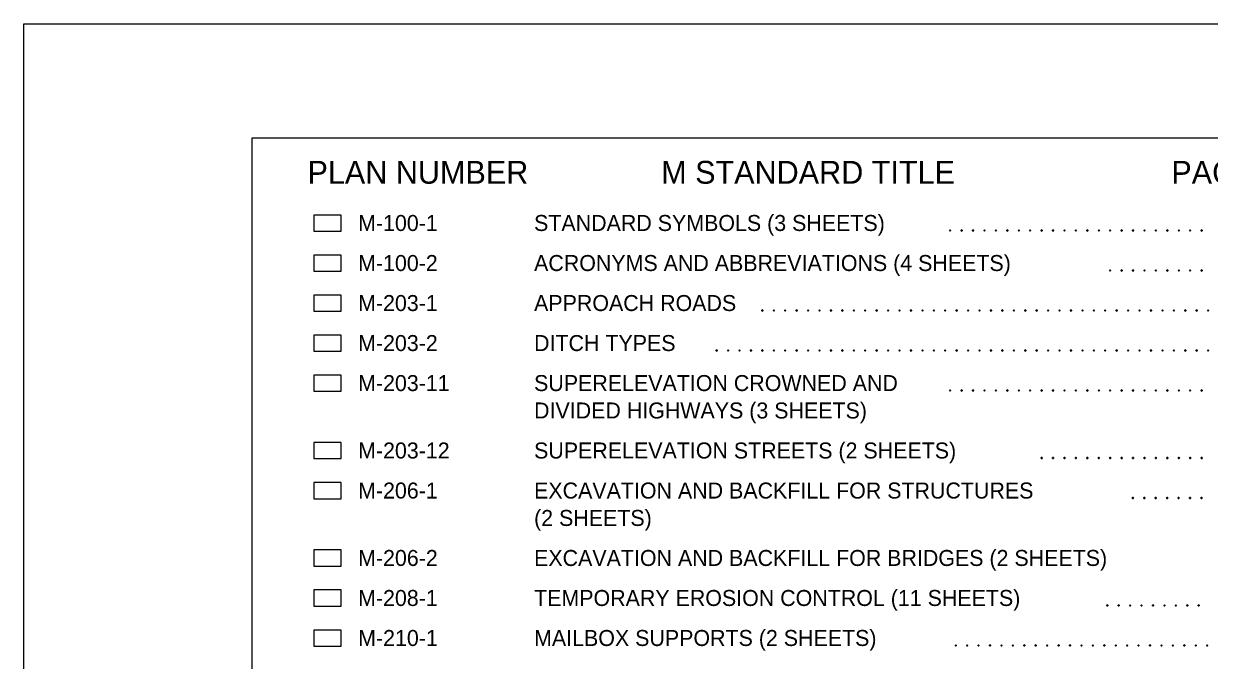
# Model space of a CAD drawing. Extents: x 0 to 1.42, y 0 to 0.92.
# Drawn here: x 0 to 0.4322, y 0.6845 to 0.9167 of the extents above; entities that cross this region are included whole.
import ezdxf

# ---------------------------------------------------------------- set-up
doc = ezdxf.new("R2010")
doc.units = 0
for name, color, linetype in [('DRAFT_Text-Notes', 7, 'Continuous'), ('DRAFT_Text-Titles', 7, 'Continuous'), ('SHEET_Lines', 7, 'Continuous'), ('SHEET_Plot Boundary', 7, 'Continuous')]:
    doc.layers.add(name, color=color, linetype=linetype)

msp = doc.modelspace()

# ---------------------------------------------------------------- linework, layer by layer
at = {"layer": 'DRAFT_Text-Notes'}
for centre in [(0.33776, 0.84128), (0.34192, 0.84128), (0.34609, 0.84128), (0.35026, 0.84128), (0.35442, 0.84128), (0.35859, 0.84128), (0.36276, 0.84128), (0.36692, 0.84128), (0.37109, 0.84128), (0.37526, 0.84128), (0.37942, 0.84128), (0.38359, 0.84128), (0.38776, 0.84128), (0.39192, 0.84128), (0.39609, 0.84128), (0.40026, 0.84128), (0.40442, 0.84128), (0.40859, 0.84128), (0.41276, 0.84128), (0.41276, 0.84128), (0.41692, 0.84128), (0.42109, 0.84128), (0.42526, 0.84128), (0.42942, 0.84128), (0.39609, 0.82669), (0.40026, 0.82669), (0.40442, 0.82669), (0.40859, 0.82669), (0.41276, 0.82669), (0.41276, 0.82669), (0.41692, 0.82669), (0.42109, 0.82669), (0.42526, 0.82669), (0.42942, 0.82669), (0.26929, 0.8121), (0.27346, 0.8121), (0.27763, 0.8121), (0.28179, 0.8121), (0.28596, 0.8121), (0.29013, 0.8121), (0.29429, 0.8121), (0.29846, 0.8121), (0.30263, 0.8121), (0.30679, 0.8121), (0.31096, 0.8121), (0.31513, 0.8121), (0.31929, 0.8121), (0.32346, 0.8121), (0.32346, 0.8121), (0.32763, 0.8121), (0.33179, 0.8121), (0.33596, 0.8121), (0.34013, 0.8121), (0.34429, 0.8121), (0.34846, 0.8121), (0.35263, 0.8121), (0.35679, 0.8121), (0.36096, 0.8121), (0.36513, 0.8121), (0.36929, 0.8121), (0.37346, 0.8121), (0.37763, 0.8121), (0.38179, 0.8121), (0.38596, 0.8121), (0.39013, 0.8121), (0.39429, 0.8121), (0.39846, 0.8121), (0.40263, 0.8121), (0.40679, 0.8121), (0.41096, 0.8121), (0.41096, 0.8121), (0.41513, 0.8121), (0.41929, 0.8121), (0.42346, 0.8121), (0.42763, 0.8121), (0.43179, 0.8121), (0.25263, 0.79751), (0.25679, 0.79751), (0.26096, 0.79751), (0.26513, 0.79751), (0.26929, 0.79751), (0.27346, 0.79751), (0.27763, 0.79751), (0.28179, 0.79751), (0.28596, 0.79751), (0.29013, 0.79751), (0.29429, 0.79751), (0.29846, 0.79751), (0.29846, 0.79751), (0.30263, 0.79751), (0.30679, 0.79751), (0.31096, 0.79751), (0.31513, 0.79751), (0.31929, 0.79751), (0.32346, 0.79751), (0.32763, 0.79751), (0.33179, 0.79751), (0.33596, 0.79751), (0.34013, 0.79751), (0.34429, 0.79751), (0.34846, 0.79751), (0.35263, 0.79751), (0.35679, 0.79751), (0.36096, 0.79751), (0.36513, 0.79751), (0.36929, 0.79751), (0.37346, 0.79751), (0.37763, 0.79751), (0.38179, 0.79751), (0.38596, 0.79751), (0.38596, 0.79751), (0.39013, 0.79751), (0.39429, 0.79751), (0.39846, 0.79751), (0.40263, 0.79751), (0.40679, 0.79751), (0.41096, 0.79751), (0.41513, 0.79751), (0.41929, 0.79751), (0.42346, 0.79751), (0.42763, 0.79751), (0.43179, 0.79751), (0.33776, 0.78292), (0.34192, 0.78292), (0.34609, 0.78292), (0.35026, 0.78292), (0.35442, 0.78292), (0.35859, 0.78292), (0.36276, 0.78292), (0.36692, 0.78292), (0.37109, 0.78292), (0.37526, 0.78292), (0.37942, 0.78292), (0.38359, 0.78292), (0.38776, 0.78292), (0.38776, 0.78292), (0.39192, 0.78292), (0.39609, 0.78292), (0.40026, 0.78292), (0.40442, 0.78292), (0.40859, 0.78292), (0.41276, 0.78292), (0.41692, 0.78292), (0.42109, 0.78292), (0.42526, 0.78292), (0.42942, 0.78292), (0.37109, 0.75832), (0.37526, 0.75832), (0.37942, 0.75832), (0.38359, 0.75832), (0.38776, 0.75832), (0.38776, 0.75832), (0.39192, 0.75832), (0.39609, 0.75832), (0.40026, 0.75832), (0.40442, 0.75832), (0.40859, 0.75832), (0.41276, 0.75832), (0.41692, 0.75832), (0.42109, 0.75832), (0.42526, 0.75832), (0.42942, 0.75832), (0.40435, 0.74373), (0.40852, 0.74373), (0.41269, 0.74373), (0.41269, 0.74373), (0.41685, 0.74373), (0.42102, 0.74373), (0.42519, 0.74373), (0.42935, 0.74373), (0.39503, 0.70455), (0.3992, 0.70455), (0.40336, 0.70455), (0.40753, 0.70455), (0.4117, 0.70455), (0.41586, 0.70455), (0.42003, 0.70455), (0.4242, 0.70455), (0.42836, 0.70455), (0.33978, 0.68996), (0.34394, 0.68996), (0.34811, 0.68996), (0.35228, 0.68996), (0.35644, 0.68996), (0.36061, 0.68996), (0.36478, 0.68996), (0.36894, 0.68996), (0.37311, 0.68996), (0.37728, 0.68996), (0.38144, 0.68996), (0.38561, 0.68996), (0.38978, 0.68996), (0.39394, 0.68996), (0.39811, 0.68996), (0.40228, 0.68996), (0.40644, 0.68996), (0.41061, 0.68996), (0.41478, 0.68996), (0.41894, 0.68996), (0.42311, 0.68996), (0.42728, 0.68996), (0.43144, 0.68996)]:
    msp.add_circle(centre, 0.000208, dxfattribs=at)
for centre, start, end in [((0.33776, 0.84128), 0, 180), ((0.33776, 0.84128), 180, 0), ((0.34192, 0.84128), 0, 180), ((0.34192, 0.84128), 180, 0), ((0.34609, 0.84128), 0, 180), ((0.34609, 0.84128), 180, 0), ((0.35026, 0.84128), 0, 180), ((0.35026, 0.84128), 180, 0), ((0.35442, 0.84128), 0, 180), ((0.35442, 0.84128), 180, 0), ((0.35859, 0.84128), 0, 180), ((0.35859, 0.84128), 180, 0), ((0.36276, 0.84128), 0, 180), ((0.36276, 0.84128), 180, 0), ((0.36692, 0.84128), 0, 180), ((0.36692, 0.84128), 180, 0), ((0.37109, 0.84128), 0, 180), ((0.37109, 0.84128), 180, 0), ((0.37526, 0.84128), 0, 180), ((0.37526, 0.84128), 180, 0), ((0.37942, 0.84128), 0, 180), ((0.37942, 0.84128), 180, 0), ((0.38359, 0.84128), 0, 180), ((0.38359, 0.84128), 180, 0), ((0.38776, 0.84128), 0, 180), ((0.38776, 0.84128), 180, 0), ((0.39192, 0.84128), 0, 180), ((0.39192, 0.84128), 180, 0), ((0.39609, 0.84128), 0, 180), ((0.39609, 0.84128), 180, 0), ((0.40026, 0.84128), 0, 180), ((0.40026, 0.84128), 180, 0), ((0.40442, 0.84128), 0, 180), ((0.40442, 0.84128), 180, 0), ((0.40859, 0.84128), 0, 180), ((0.40859, 0.84128), 180, 0), ((0.41276, 0.84128), 0, 180), ((0.41276, 0.84128), 0, 180), ((0.41276, 0.84128), 180, 0), ((0.41276, 0.84128), 180, 0), ((0.41692, 0.84128), 0, 180), ((0.41692, 0.84128), 180, 0), ((0.42109, 0.84128), 0, 180), ((0.42109, 0.84128), 180, 0), ((0.42526, 0.84128), 0, 180), ((0.42526, 0.84128), 180, 0), ((0.42942, 0.84128), 0, 180), ((0.42942, 0.84128), 180, 0), ((0.39609, 0.82669), 0, 180), ((0.39609, 0.82669), 180, 0), ((0.40026, 0.82669), 0, 180), ((0.40026, 0.82669), 180, 0), ((0.40442, 0.82669), 0, 180), ((0.40442, 0.82669), 180, 0), ((0.40859, 0.82669), 0, 180), ((0.40859, 0.82669), 180, 0), ((0.41276, 0.82669), 0, 180), ((0.41276, 0.82669), 0, 180), ((0.41276, 0.82669), 180, 0), ((0.41276, 0.82669), 180, 0), ((0.41692, 0.82669), 0, 180), ((0.41692, 0.82669), 180, 0), ((0.42109, 0.82669), 0, 180), ((0.42109, 0.82669), 180, 0), ((0.42526, 0.82669), 0, 180), ((0.42526, 0.82669), 180, 0), ((0.42942, 0.82669), 0, 180), ((0.42942, 0.82669), 180, 0), ((0.26929, 0.8121), 0, 180), ((0.26929, 0.8121), 180, 0), ((0.27346, 0.8121), 0, 180), ((0.27346, 0.8121), 180, 0), ((0.27763, 0.8121), 0, 180), ((0.27763, 0.8121), 180, 0), ((0.28179, 0.8121), 0, 180), ((0.28179, 0.8121), 180, 0), ((0.28596, 0.8121), 0, 180), ((0.28596, 0.8121), 180, 0), ((0.29013, 0.8121), 0, 180), ((0.29013, 0.8121), 180, 0), ((0.29429, 0.8121), 0, 180), ((0.29429, 0.8121), 180, 0), ((0.29846, 0.8121), 0, 180), ((0.29846, 0.8121), 180, 0), ((0.30263, 0.8121), 0, 180), ((0.30263, 0.8121), 180, 0), ((0.30679, 0.8121), 0, 180), ((0.30679, 0.8121), 180, 0), ((0.31096, 0.8121), 0, 180), ((0.31096, 0.8121), 180, 0), ((0.31513, 0.8121), 0, 180), ((0.31513, 0.8121), 180, 0), ((0.31929, 0.8121), 0, 180), ((0.31929, 0.8121), 180, 0), ((0.32346, 0.8121), 0, 180), ((0.32346, 0.8121), 0, 180), ((0.32346, 0.8121), 180, 0), ((0.32346, 0.8121), 180, 0), ((0.32763, 0.8121), 0, 180), ((0.32763, 0.8121), 180, 0), ((0.33179, 0.8121), 0, 180), ((0.33179, 0.8121), 180, 0), ((0.33596, 0.8121), 0, 180), ((0.33596, 0.8121), 180, 0), ((0.34013, 0.8121), 0, 180), ((0.34013, 0.8121), 180, 0), ((0.34429, 0.8121), 0, 180), ((0.34429, 0.8121), 180, 0), ((0.34846, 0.8121), 0, 180), ((0.34846, 0.8121), 180, 0), ((0.35263, 0.8121), 0, 180), ((0.35263, 0.8121), 180, 0), ((0.35679, 0.8121), 0, 180), ((0.35679, 0.8121), 180, 0), ((0.36096, 0.8121), 0, 180), ((0.36096, 0.8121), 180, 0), ((0.36513, 0.8121), 0, 180), ((0.36513, 0.8121), 180, 0), ((0.36929, 0.8121), 0, 180), ((0.36929, 0.8121), 180, 0), ((0.37346, 0.8121), 0, 180), ((0.37346, 0.8121), 180, 0), ((0.37763, 0.8121), 0, 180), ((0.37763, 0.8121), 180, 0), ((0.38179, 0.8121), 0, 180), ((0.38179, 0.8121), 180, 0), ((0.38596, 0.8121), 0, 180), ((0.38596, 0.8121), 180, 0), ((0.39013, 0.8121), 0, 180), ((0.39013, 0.8121), 180, 0), ((0.39429, 0.8121), 0, 180), ((0.39429, 0.8121), 180, 0), ((0.39846, 0.8121), 0, 180), ((0.39846, 0.8121), 180, 0), ((0.40263, 0.8121), 0, 180), ((0.40263, 0.8121), 180, 0), ((0.40679, 0.8121), 0, 180), ((0.40679, 0.8121), 180, 0), ((0.41096, 0.8121), 0, 180), ((0.41096, 0.8121), 0, 180), ((0.41096, 0.8121), 180, 0), ((0.41096, 0.8121), 180, 0), ((0.41513, 0.8121), 0, 180), ((0.41513, 0.8121), 180, 0), ((0.41929, 0.8121), 0, 180), ((0.41929, 0.8121), 180, 0), ((0.42346, 0.8121), 0, 180), ((0.42346, 0.8121), 180, 0), ((0.42763, 0.8121), 0, 180), ((0.42763, 0.8121), 180, 0), ((0.43179, 0.8121), 0, 180), ((0.43179, 0.8121), 180, 0), ((0.25263, 0.79751), 0, 180), ((0.25263, 0.79751), 180, 0), ((0.25679, 0.79751), 0, 180), ((0.25679, 0.79751), 180, 0), ((0.26096, 0.79751), 0, 180), ((0.26096, 0.79751), 180, 0), ((0.26513, 0.79751), 0, 180), ((0.26513, 0.79751), 180, 0), ((0.26929, 0.79751), 0, 180), ((0.26929, 0.79751), 180, 0), ((0.27346, 0.79751), 0, 180), ((0.27346, 0.79751), 180, 0), ((0.27763, 0.79751), 0, 180), ((0.27763, 0.79751), 180, 0), ((0.28179, 0.79751), 0, 180), ((0.28179, 0.79751), 180, 0), ((0.28596, 0.79751), 0, 180), ((0.28596, 0.79751), 180, 0), ((0.29013, 0.79751), 0, 180), ((0.29013, 0.79751), 180, 0), ((0.29429, 0.79751), 0, 180), ((0.29429, 0.79751), 180, 0), ((0.29846, 0.79751), 0, 180), ((0.29846, 0.79751), 0, 180), ((0.29846, 0.79751), 180, 0), ((0.29846, 0.79751), 180, 0), ((0.30263, 0.79751), 0, 180), ((0.30263, 0.79751), 180, 0), ((0.30679, 0.79751), 0, 180), ((0.30679, 0.79751), 180, 0), ((0.31096, 0.79751), 0, 180), ((0.31096, 0.79751), 180, 0), ((0.31513, 0.79751), 0, 180), ((0.31513, 0.79751), 180, 0), ((0.31929, 0.79751), 0, 180), ((0.31929, 0.79751), 180, 0), ((0.32346, 0.79751), 0, 180), ((0.32346, 0.79751), 180, 0), ((0.32763, 0.79751), 0, 180), ((0.32763, 0.79751), 180, 0), ((0.33179, 0.79751), 0, 180), ((0.33179, 0.79751), 180, 0), ((0.33596, 0.79751), 0, 180), ((0.33596, 0.79751), 180, 0), ((0.34013, 0.79751), 0, 180), ((0.34013, 0.79751), 180, 0), ((0.34429, 0.79751), 0, 180), ((0.34429, 0.79751), 180, 0), ((0.34846, 0.79751), 0, 180), ((0.34846, 0.79751), 180, 0), ((0.35263, 0.79751), 0, 180), ((0.35263, 0.79751), 180, 0), ((0.35679, 0.79751), 0, 180), ((0.35679, 0.79751), 180, 0), ((0.36096, 0.79751), 0, 180), ((0.36096, 0.79751), 180, 0), ((0.36513, 0.79751), 0, 180), ((0.36513, 0.79751), 180, 0), ((0.36929, 0.79751), 0, 180), ((0.36929, 0.79751), 180, 0), ((0.37346, 0.79751), 0, 180), ((0.37346, 0.79751), 180, 0), ((0.37763, 0.79751), 0, 180), ((0.37763, 0.79751), 180, 0), ((0.38179, 0.79751), 0, 180), ((0.38179, 0.79751), 180, 0), ((0.38596, 0.79751), 0, 180), ((0.38596, 0.79751), 0, 180), ((0.38596, 0.79751), 180, 0), ((0.38596, 0.79751), 180, 0), ((0.39013, 0.79751), 0, 180), ((0.39013, 0.79751), 180, 0), ((0.39429, 0.79751), 0, 180), ((0.39429, 0.79751), 180, 0), ((0.39846, 0.79751), 0, 180), ((0.39846, 0.79751), 180, 0), ((0.40263, 0.79751), 0, 180), ((0.40263, 0.79751), 180, 0), ((0.40679, 0.79751), 0, 180), ((0.40679, 0.79751), 180, 0), ((0.41096, 0.79751), 0, 180), ((0.41096, 0.79751), 180, 0), ((0.41513, 0.79751), 0, 180), ((0.41513, 0.79751), 180, 0), ((0.41929, 0.79751), 0, 180), ((0.41929, 0.79751), 180, 0), ((0.42346, 0.79751), 0, 180), ((0.42346, 0.79751), 180, 0), ((0.42763, 0.79751), 0, 180), ((0.42763, 0.79751), 180, 0), ((0.43179, 0.79751), 0, 180), ((0.43179, 0.79751), 180, 0), ((0.33776, 0.78292), 0, 180), ((0.33776, 0.78292), 180, 0), ((0.34192, 0.78292), 0, 180), ((0.34192, 0.78292), 180, 0), ((0.34609, 0.78292), 0, 180), ((0.34609, 0.78292), 180, 0), ((0.35026, 0.78292), 0, 180), ((0.35026, 0.78292), 180, 0), ((0.35442, 0.78292), 0, 180), ((0.35442, 0.78292), 180, 0), ((0.35859, 0.78292), 0, 180), ((0.35859, 0.78292), 180, 0), ((0.36276, 0.78292), 0, 180), ((0.36276, 0.78292), 180, 0), ((0.36692, 0.78292), 0, 180), ((0.36692, 0.78292), 180, 0), ((0.37109, 0.78292), 0, 180), ((0.37109, 0.78292), 180, 0), ((0.37526, 0.78292), 0, 180), ((0.37526, 0.78292), 180, 0), ((0.37942, 0.78292), 0, 180), ((0.37942, 0.78292), 180, 0), ((0.38359, 0.78292), 0, 180), ((0.38359, 0.78292), 180, 0), ((0.38776, 0.78292), 0, 180), ((0.38776, 0.78292), 0, 180), ((0.38776, 0.78292), 180, 0), ((0.38776, 0.78292), 180, 0), ((0.39192, 0.78292), 0, 180), ((0.39192, 0.78292), 180, 0), ((0.39609, 0.78292), 0, 180), ((0.39609, 0.78292), 180, 0), ((0.40026, 0.78292), 0, 180), ((0.40026, 0.78292), 180, 0), ((0.40442, 0.78292), 0, 180), ((0.40442, 0.78292), 180, 0), ((0.40859, 0.78292), 0, 180), ((0.40859, 0.78292), 180, 0), ((0.41276, 0.78292), 0, 180), ((0.41276, 0.78292), 180, 0), ((0.41692, 0.78292), 0, 180), ((0.41692, 0.78292), 180, 0), ((0.42109, 0.78292), 0, 180), ((0.42109, 0.78292), 180, 0), ((0.42526, 0.78292), 0, 180), ((0.42526, 0.78292), 180, 0), ((0.42942, 0.78292), 0, 180), ((0.42942, 0.78292), 180, 0), ((0.37109, 0.75832), 0, 180), ((0.37109, 0.75832), 180, 0), ((0.37526, 0.75832), 0, 180), ((0.37526, 0.75832), 180, 0), ((0.37942, 0.75832), 0, 180), ((0.37942, 0.75832), 180, 0), ((0.38359, 0.75832), 0, 180), ((0.38359, 0.75832), 180, 0), ((0.38776, 0.75832), 0, 180), ((0.38776, 0.75832), 0, 180), ((0.38776, 0.75832), 180, 0), ((0.38776, 0.75832), 180, 0), ((0.39192, 0.75832), 0, 180), ((0.39192, 0.75832), 180, 0), ((0.39609, 0.75832), 0, 180), ((0.39609, 0.75832), 180, 0), ((0.40026, 0.75832), 0, 180), ((0.40026, 0.75832), 180, 0), ((0.40442, 0.75832), 0, 180), ((0.40442, 0.75832), 180, 0), ((0.40859, 0.75832), 0, 180), ((0.40859, 0.75832), 180, 0), ((0.41276, 0.75832), 0, 180), ((0.41276, 0.75832), 180, 0), ((0.41692, 0.75832), 0, 180), ((0.41692, 0.75832), 180, 0), ((0.42109, 0.75832), 0, 180), ((0.42109, 0.75832), 180, 0), ((0.42526, 0.75832), 0, 180), ((0.42526, 0.75832), 180, 0), ((0.42942, 0.75832), 0, 180), ((0.42942, 0.75832), 180, 0), ((0.40435, 0.74373), 0, 180), ((0.40435, 0.74373), 180, 0), ((0.40852, 0.74373), 0, 180), ((0.40852, 0.74373), 180, 0), ((0.41269, 0.74373), 0, 180), ((0.41269, 0.74373), 0, 180), ((0.41269, 0.74373), 180, 0), ((0.41269, 0.74373), 180, 0), ((0.41685, 0.74373), 0, 180), ((0.41685, 0.74373), 180, 0), ((0.42102, 0.74373), 0, 180), ((0.42102, 0.74373), 180, 0), ((0.42519, 0.74373), 0, 180), ((0.42519, 0.74373), 180, 0), ((0.42935, 0.74373), 0, 180), ((0.42935, 0.74373), 180, 0), ((0.39503, 0.70455), 0, 180), ((0.39503, 0.70455), 180, 0), ((0.3992, 0.70455), 0, 180), ((0.3992, 0.70455), 180, 0), ((0.40336, 0.70455), 0, 180), ((0.40336, 0.70455), 180, 0), ((0.40753, 0.70455), 0, 180), ((0.40753, 0.70455), 180, 0), ((0.4117, 0.70455), 0, 180), ((0.4117, 0.70455), 180, 0), ((0.41586, 0.70455), 0, 180), ((0.41586, 0.70455), 180, 0), ((0.42003, 0.70455), 0, 180), ((0.42003, 0.70455), 180, 0), ((0.4242, 0.70455), 0, 180), ((0.4242, 0.70455), 180, 0), ((0.42836, 0.70455), 0, 180), ((0.42836, 0.70455), 180, 0), ((0.33978, 0.68996), 0, 180), ((0.33978, 0.68996), 180, 0), ((0.34394, 0.68996), 0, 180), ((0.34394, 0.68996), 180, 0), ((0.34811, 0.68996), 0, 180), ((0.34811, 0.68996), 180, 0), ((0.35228, 0.68996), 0, 180), ((0.35228, 0.68996), 180, 0), ((0.35644, 0.68996), 0, 180), ((0.35644, 0.68996), 180, 0), ((0.36061, 0.68996), 0, 180), ((0.36061, 0.68996), 180, 0), ((0.36478, 0.68996), 0, 180), ((0.36478, 0.68996), 180, 0), ((0.36894, 0.68996), 0, 180), ((0.36894, 0.68996), 180, 0), ((0.37311, 0.68996), 0, 180), ((0.37311, 0.68996), 180, 0), ((0.37728, 0.68996), 0, 180), ((0.37728, 0.68996), 180, 0), ((0.38144, 0.68996), 0, 180), ((0.38144, 0.68996), 180, 0), ((0.38561, 0.68996), 0, 180), ((0.38561, 0.68996), 180, 0), ((0.38978, 0.68996), 0, 180), ((0.38978, 0.68996), 180, 0), ((0.39394, 0.68996), 0, 180), ((0.39394, 0.68996), 180, 0), ((0.39811, 0.68996), 0, 180), ((0.39811, 0.68996), 180, 0), ((0.40228, 0.68996), 0, 180), ((0.40228, 0.68996), 180, 0), ((0.40644, 0.68996), 0, 180), ((0.40644, 0.68996), 180, 0), ((0.41061, 0.68996), 0, 180), ((0.41061, 0.68996), 180, 0), ((0.41478, 0.68996), 0, 180), ((0.41478, 0.68996), 180, 0), ((0.41894, 0.68996), 0, 180), ((0.41894, 0.68996), 180, 0), ((0.42311, 0.68996), 0, 180), ((0.42311, 0.68996), 180, 0), ((0.42728, 0.68996), 0, 180), ((0.42728, 0.68996), 180, 0), ((0.43144, 0.68996), 0, 180), ((0.43144, 0.68996), 180, 0)]:
    msp.add_arc(centre, 0.000208, start, end, dxfattribs=at)
at = {"layer": 'SHEET_Lines'}
msp.add_lwpolyline([(0.08333, 0.875), (1.375, 0.875), (1.375, 0.125), (0.08333, 0.125)], close=True, dxfattribs=at)
for points in [[(0.10578, 0.84102), (0.11575, 0.84102), (0.11575, 0.84691), (0.10578, 0.84691), (0.10578, 0.84102)], [(0.10578, 0.82643), (0.11575, 0.82643), (0.11575, 0.83232), (0.10578, 0.83232), (0.10578, 0.82643)], [(0.10578, 0.81184), (0.11575, 0.81184), (0.11575, 0.81773), (0.10578, 0.81773), (0.10578, 0.81184)], [(0.10578, 0.79725), (0.11575, 0.79725), (0.11575, 0.80313), (0.10578, 0.80313), (0.10578, 0.79725)], [(0.10578, 0.78266), (0.11575, 0.78266), (0.11575, 0.78854), (0.10578, 0.78854), (0.10578, 0.78266)], [(0.10578, 0.75806), (0.11575, 0.75806), (0.11575, 0.76395), (0.10578, 0.76395), (0.10578, 0.75806)], [(0.10578, 0.74347), (0.11575, 0.74347), (0.11575, 0.74936), (0.10578, 0.74936), (0.10578, 0.74347)], [(0.10578, 0.71888), (0.11575, 0.71888), (0.11575, 0.72477), (0.10578, 0.72477), (0.10578, 0.71888)], [(0.10578, 0.70429), (0.11575, 0.70429), (0.11575, 0.71017), (0.10578, 0.71017), (0.10578, 0.70429)], [(0.10579, 0.68969), (0.11576, 0.68969), (0.11576, 0.69558), (0.10579, 0.69558), (0.10579, 0.68969)]]:
    msp.add_lwpolyline(points, dxfattribs=at)
at = {"layer": 'SHEET_Plot Boundary'}
msp.add_lwpolyline([(0, 0.91667), (1.41667, 0.91667), (1.41667, 0), (0, 0)], close=True, dxfattribs=at)

# ---------------------------------------------------------------- texts
at = {"layer": 'DRAFT_Text-Notes'}
for s, height, p in [('STANDARD SYMBOLS (3 SHEETS)', 0.0058333, (0.18606, 0.84108)), ('M-100-1', 0.005833, (0.1219, 0.84108)), ('M-100-2', 0.005833, (0.1219, 0.82648)), ('ACRONYMS AND ABBREVIATIONS (4 SHEETS)', 0.0058333, (0.18606, 0.82648)), ('M-203-1', 0.005833, (0.1219, 0.81189)), ('APPROACH ROADS', 0.0058333, (0.18606, 0.81189)), ('M-203-2', 0.005833, (0.1219, 0.7973)), ('DITCH TYPES', 0.0058333, (0.18606, 0.7973)), ('M-203-11', 0.005833, (0.1219, 0.78271)), ('SUPERELEVATION CROWNED AND', 0.0058333, (0.18606, 0.78271)), ('DIVIDED HIGHWAYS (3 SHEETS)', 0.0058333, (0.18606, 0.77271)), ('M-203-12', 0.005833, (0.1219, 0.75812)), ('SUPERELEVATION STREETS (2 SHEETS)', 0.0058333, (0.18606, 0.75812)), ('M-206-1', 0.005833, (0.1219, 0.74352)), ('EXCAVATION AND BACKFILL FOR STRUCTURES', 0.0058333, (0.18606, 0.74352)), ('(2 SHEETS)', 0.005833, (0.18606, 0.73352)), ('M-206-2', 0.005833, (0.1219, 0.71893)), ('EXCAVATION AND BACKFILL FOR BRIDGES (2 SHEETS)', 0.0058333, (0.18606, 0.71893)), ('M-208-1', 0.005833, (0.1219, 0.70434)), ('TEMPORARY EROSION CONTROL (11 SHEETS)', 0.0058333, (0.18606, 0.70434)), ('MAILBOX SUPPORTS (2 SHEETS)', 0.0058333, (0.18606, 0.68975)), ('M-210-1', 0.005833, (0.12192, 0.68975))]:
    msp.add_text(s, height=height, dxfattribs=at).set_placement(p)
at = {"layer": 'DRAFT_Text-Titles'}
for s, p in [('PLAN NUMBER', (0.10345, 0.85831)), ('M STANDARD TITLE', (0.23239, 0.85831)), ('PAGE NUMBER', (0.41838, 0.85831))]:
    msp.add_text(s, height=0.0083333, dxfattribs=at).set_placement(p)

doc.saveas('drawing.dxf')
